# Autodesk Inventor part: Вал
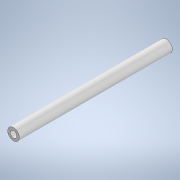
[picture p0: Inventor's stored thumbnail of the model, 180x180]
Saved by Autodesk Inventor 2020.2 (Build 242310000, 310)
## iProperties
Created: 2020-04
Part Number: Вал
Material: Типовые
Document SubType Name: Modeling
Designer: Алексей
Density: 1 g/cm^3
Appearance: По умолчанию
Author: Алексей
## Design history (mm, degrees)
sketch "Эскиз1"
  geometry: C1 r 2.75 at (0, 0.75) reference; C2 r 2.5 at (0, 0.75); 1 further point
  constraints: 1 centre point, 1 coincident
  dimensions: "d0" = 5 diameter of C2
  node "Ссылка1"
node "РабПлоскость1"
extrude "Выдавливание1" new body sketch "Эскиз1" stored distance "d1" = 10; taper "d2" = 0 deg
sketch "Эскиз2"
  geometry: C1 r 2.5 at (0, 0) reference; 1 further point
extrude "Выдавливание2" join sketch "Эскиз2" distance "d3" = 4; taper "d4" = 0 deg
sketch "Эскиз3"
  geometry: C1 r 2.5 at (0, 0) reference; 1 further point
extrude "Выдавливание3" join sketch "Эскиз3" distance "d5" = 4; taper "d6" = 0 deg
sketch "Эскиз4"
  geometry: C1 r 2.5 at (0, 0) reference; C2 r 1.4 at (0, 0); 1 further point
  constraints: 1 centre point, 1 coincident
  dimensions: "d7" = 2.8 diameter of C2
extrude "Выдавливание4" cut sketch "Эскиз4" distance "d8" = 10; taper "d9" = 0 deg
sketch "Эскиз5"
  geometry: C1 r 1.4 at (0, 0); 1 further point
  constraints: 1 centre point
  dimensions: "d10" = 2.8 diameter of C1
extrude "Выдавливание5" cut sketch "Эскиз5" distance "d11" = 10; taper "d12" = 0 deg
node "Твердое тело1"
node "Спроецированная петля1"
node "Спроецированная петля2"
